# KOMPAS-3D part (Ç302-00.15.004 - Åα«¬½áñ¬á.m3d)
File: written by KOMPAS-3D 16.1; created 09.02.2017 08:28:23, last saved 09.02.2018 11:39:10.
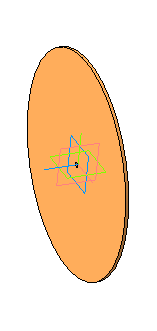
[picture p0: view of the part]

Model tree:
1. Эскиз:7
2. Операция выдавливания:12
     Расстояние 1 = 4; Расстояние 2 = 24.8832
3. Эскиз:8
4. Вырезать элемент выдавливания:1
     Расстояние 1 = 0.1
5. Зеркальный массив:1
6. Экземпляр ( 1 )
7. Экземпляр ( 2 )  (with: Вырезать элемент выдавливания:1)  (labels: А302-00.15.001)

Expressions: 250+28
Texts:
  Body Specification ( left align )
  Body Specificaton ( centered )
